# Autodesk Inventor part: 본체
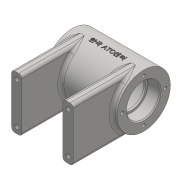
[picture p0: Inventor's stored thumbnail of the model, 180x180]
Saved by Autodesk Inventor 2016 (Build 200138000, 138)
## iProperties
Created: 2020-07
Part Number: 본체
Material: Generic
Document SubType Name: Modeling
Designer: USER
Density: 1 g/cm^3
Appearance: Default
Author: USER
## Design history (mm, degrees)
sketch "스케치1"
  geometry: L1 (-35, 0)-(35, 0); L2 (-35, 0)-(-35, 26); L3 (-35, 26)-(35, 26); L4 (35, 26)-(35, 0); L5 (-35, 16)-(-23, 16); L6 (-23, 16)-(-23, 14); L7 (-23, 14)-(-21, 14); L8 (-21, 14)-(-21, 21); L9 (-21, 21)-(21, 21); L10 (21, 21)-(21, 14); L11 (21, 14)-(23, 14); L12 (23, 14)-(23, 16); L13 (23, 16)-(35, 16); 2 further points
  constraints: 26 end point, 10 perpendicular, 2 horizontal, 2 point on line, 1 coincident, 1 midpoint, 1 vertical
  dimensions: "d0" = 32 diameter of L5 L1; "d1" = 28 diameter of L7 L1; "d2" = 42 diameter of L9 L1; "d3" = 28 diameter of L11 L1; "d4" = 32 diameter of L13 L1; "d5" = 52 diameter of L3 L1; "d6" = 12 distance of L5.start L5.end; "d7" = 2 distance of L6.end L7.end; "d8" = 12 distance of L12.end L13.end; "d9" = 42 distance of L8.end L9.end; "d10" = 2 distance of L10.end L11.end
revolve "회전1" sketch "스케치1" stored, may be unused: angle "d11" = 90 deg
node "작업 평면1"
sketch "스케치2"
  geometry: L1 (0, -26)-(-64, -26); L2 (-64, -26)-(-64, 26); L3 (-64, 26)-(0, 26); A1 r 26 centre (0, 0) between (0, -26) and (0, 26) reference; 2 further points
  constraints: 6 end point, 2 perpendicular, 2 point on circle, 1 horizontal, 1 horizontal alignment, 1 midpoint
  dimensions: "d13" = 52 distance of L1.end L2.end; "d60" = 64 distance from line of L2 point (0, 0)
extrude "돌출1" join sketch "스케치2" distance "d14" = 10; taper "d15" = 0 deg
node "작업 평면2"
sketch "스케치3"
  geometry: C1 r 5 at (0, 0); 1 further point
  constraints: 1 centre point, 1 coincident
  dimensions: "d17" = 10 diameter of C1
extrude "돌출2" join sketch "스케치3" stored distance "d18" = 10; taper "d19" = 0 deg
sketch "스케치4"
  geometry: 1 further point
hole "구멍1" sketch "스케치4" at (0, 0) diameter "d20" = 5.188; stored, may be unused: countersink angle "d24" = 90 deg, drill point angle "d26" = 118 deg; dims "d21" = 12, "d22" = 4, "d23" = 2, "d25" = 16
sketch "스케치5"
  geometry: L1 (29, -5)-(25.515, -5) reference; L2 (25.515, 5)-(29, 5) reference; L3 (29, 5)-(29, 2.594) reference; L4 (29, 2.594)-(20.839, 2.594) reference; L5 (20.839, -2.594)-(29, -2.594) reference; L6 (29, -2.594)-(29, -5) reference; L7 (0, 0)-(-27.251, -9.919); L8 (0, 0)-(-26, 0); L9 (-27.251, -9.919)-(-29.303, -4.28); L10 (-29.303, -4.28)-(-25.825, -3.014); A1 r 26 centre (0, 0) between (25.515, 5) and (25.515, -5) reference; A2 r 21 centre (0, 0) between (20.839, 2.594) and (20.839, -2.594) reference; A3 r 26 centre (0, 0) between (0, 26) and (0, -26) reference; A4 r 26 centre (0, 0) between (-26, 0) and (-24.432, -8.893); 1 further point
  constraints: 10 end point, 3 point on circle, 2 perpendicular, 1 centre point, 1 coincident, 1 horizontal, 1 point on line
  dimensions: "d27" = 20 deg angle of L8 L7; "d28" = 29 distance of L7.end point (0, 0); "d30" = 12 diameter of L10 L7
revolve "회전2" sketch "스케치5" stored, may be unused: angle "d29" = 90 deg
sketch "스케치6"
  geometry: 1 further point
hole "구멍2" sketch "스케치6" at (0, 0) diameter "d31" = 5.188; stored, may be unused: countersink angle "d35" = 90 deg, drill point angle "d37" = 118 deg; dims "d32" = 12, "d33" = 4, "d34" = 2, "d36" = 16
sketch "스케치7"
  geometry: L1 (-50, 0)-(-60, 0) reference; L2 (-60, 0)-(-60, 52) reference; L3 (-60, 52)-(-50, 52) reference; L4 (-50, 52)-(-50, 0) reference; L5 (0, 0)-(-10, 0) reference; L6 (-10, 0)-(-10, 52) reference; L7 (-10, 52)-(0, 52) reference; L8 (0, 52)-(0, 0) reference; L9 (-5, 6)-(-5, 46); 2 further points
  constraints: 2 end point, 1 horizontal alignment, 1 midpoint, 1 vertical
  dimensions: "d38" = 40 distance of L9.start L9.end; "d39" = 5 distance between parallel lines of L8 L9
hole "구멍3" sketch "스케치7" at (-5, 6), (-5, 46) diameter "d40" = 4.134; stored, may be unused: countersink angle "d44" = 90 deg, drill point angle "d46" = 118 deg; dims "d41" = 8, "d42" = 4, "d43" = 2, "d45" = 10
sketch "스케치8"
  geometry: L1 (0, 0)-(0, 21)
  constraints: 2 end point, 1 vertical
  dimensions: "d47" = 21 distance of L1.start L1.end
hole "구멍4" sketch "스케치8" at (0, 21) diameter "d48" = 3.242; stored, may be unused: countersink angle "d52" = 90 deg, drill point angle "d54" = 118 deg; dims "d49" = 8, "d50" = 4, "d51" = 2, "d53" = 10
sketch "스케치9"
  geometry: L1 (-5, 38)-(-5, 90) reference; L2 (60, 0)-(50, 0) reference; L3 (50, 0)-(50, 64) reference; L4 (50, 64)-(60, 64) reference; L5 (60, 64)-(65, 64) reference; L6 (60, 64)-(60, 0) reference; L7 (10, 64)-(50, 64) reference; L8 (0, 64)-(10, 64) reference; L9 (-5, 64)-(0, 64) reference; L10 (10, 64)-(10, 0) reference; L11 (10, 0)-(0, 0) reference; L12 (0, 0)-(0, 64) reference; 2 further points
  constraints: 1 other
  dimensions: "d69" = 35 distance from line of L1 point (30, 64); "d70" = 26 vertical distance of L1.end point (30, 64)
feature "엠보싱1" sketch "스케치9" dims "d0" = 32, "d1" = 28, "d2" = 42, "d3" = 28, "d4" = 32, "d5" = 52, "d6" = 12, "d7" = 2, "d8" = 12, "d9" = 42, "d10" = 2, "d13" = 52, "d58" = 0.5, "d59" = 0, "d60" = 64
fillet "모깎기1" dims "d61" = 3
fillet "모깎기2" dims "d62" = 3
fillet "모깎기3" dims "d63" = 2
fillet "모깎기4" dims "d64" = 0.3
fillet "모깎기5" dims "d65" = 3
chamfer "모따기1" distance "d66" = 1; stored, may be unused: second distance "d67" = 2, angle "d68" = 45 deg
node "솔리드1"
mirror "대칭1"
mirror "대칭2"
pattern_circular "원형 패턴1" dims angle "d56" = 360 deg
mirror "대칭3"
node "절단 모서리 투영1"
node "절단 모서리 투영2"
node "절단 모서리 투영3"
other parameters: "d16" = 29
